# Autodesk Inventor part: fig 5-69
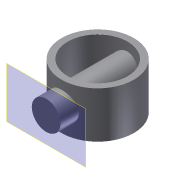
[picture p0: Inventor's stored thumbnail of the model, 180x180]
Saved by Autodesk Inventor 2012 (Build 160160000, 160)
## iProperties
Shininess: 64.0
Length Units: 11269
Angle Units: 11279
Time Units: 11290
Mass Units: 11283
Length Display Precision: 3
Angle Display Precision: 2
Compacted: True
Part Number: fig 5-69
Document SubType Name: Modeling
Created: 2002-12
Designer: deepak
Density: 1 g/cm^3
Material: Default
Density: 0.0
Volumn: 0.0
Area: 0.0
PropertySet Name: Model Information
Control State: 0
Master: False
Checked Out: False
Author: deepak
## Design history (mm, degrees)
sketch "Sketch1"
  geometry: C1 r 23.454 at (0, 0); C2 r 19.43 at (0, 0)
  constraints: 2 centre point, 1 coincident, 1 concentric
extrude "Extrusion1" new body sketch "Sketch1" stored distance "d0" = 30; taper "d1" = 0 deg
workplane "Work Plane1"
workplane "Work Plane2"
sketch "Sketch2"
  geometry: C1 r 9.343 at (0, 0)
  constraints: 1 centre point
extrude "Extrusion2" join sketch "Sketch2" stored distance "d4" = 10; taper "d5" = 0 deg
body "Solid1"
